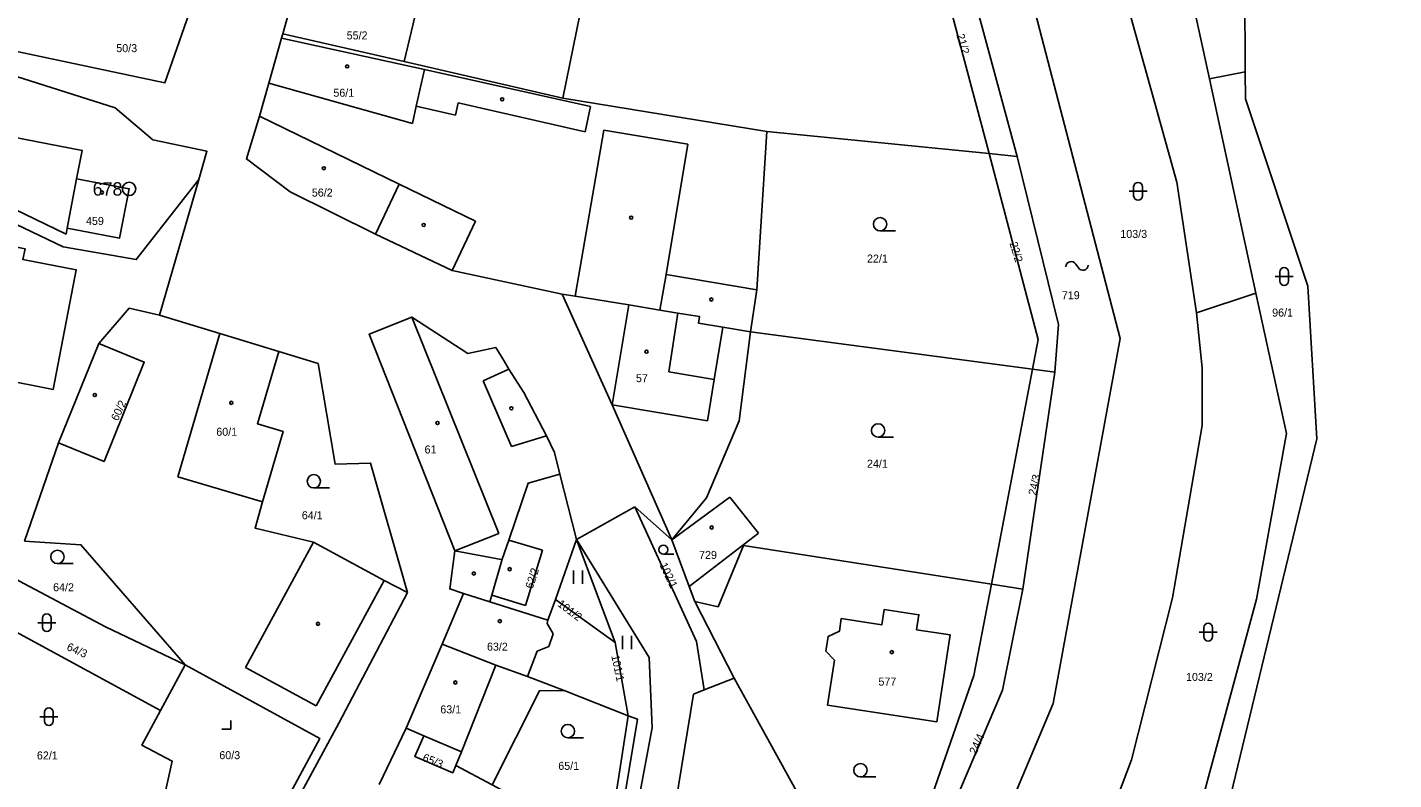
# Model space of a CAD drawing. Extents: x -758582 to -751794, y -998770 to -994350.
# Drawn here: x -755599.9 to -755446.2, y -995816.3 to -995731.7 of the extents above; entities that cross this region are included whole.
import ezdxf

# ---------------------------------------------------------------- set-up
doc = ezdxf.new("R2010")
doc.units = 0
for name, color, linetype in [('Hranice parcel', 7, 'Continuous'), ('Parcelní čísla', 7, 'Continuous'), ('Vnitřní kresba', 7, 'Continuous'), ('Značky bodu BP', 7, 'Continuous'), ('Značky budov', 7, 'Continuous'), ('Značky kultur', 7, 'Continuous')]:
    doc.layers.add(name, color=color, linetype=linetype)

msp = doc.modelspace()

# ---------------------------------------------------------------- linework, layer by layer
at = {"layer": 'Hranice parcel'}
for p, q in [((-755539.7, -995739.68), (-755534.54, -995714.36)), ((-755569.33, -995725.58), (-755571.19, -995732.43)), ((-755571.19, -995732.43), (-755557.56, -995735.57)), ((-755557.56, -995735.57), (-755539.7, -995739.68)), ((-755462.93, -995736.73), (-755466.97, -995737.5)), ((-755466.97, -995737.5), (-755461.74, -995761.6)), ((-755516.76, -995743.43), (-755539.7, -995739.68)), ((-755516.76, -995743.43), (-755491.76, -995745.91)), ((-755491.76, -995745.91), (-755488.58, -995746.23)), ((-755594.4, -995748.74), (-755595.48, -995754.29)), ((-755585.08, -995764.1), (-755580.66, -995748.82)), ((-755461.74, -995761.6), (-755468.42, -995763.84)), ((-755486.86, -995770.17), (-755518.61, -995765.97)), ((-755591.92, -995767.28), (-755596.45, -995778.47)), ((-755491.49, -995794.37), (-755486.86, -995770.17)), ((-755486.86, -995770.17), (-755484.37, -995770.5)), ((-755487.94, -995794.93), (-755484.37, -995770.5)), ((-755596.45, -995778.47), (-755600.27, -995789.5)), ((-755538.17, -995789.33), (-755540.04, -995781.97)), ((-755538.17, -995789.33), (-755531.61, -995785.64)), ((-755527.46, -995789.37), (-755531.61, -995785.64)), ((-755527.46, -995789.37), (-755520.93, -995784.58)), ((-755520.93, -995784.58), (-755517.71, -995788.63)), ((-755517.71, -995788.63), (-755525.51, -995794.6)), ((-755540.55, -995796.06), (-755538.17, -995789.33)), ((-755538.17, -995789.33), (-755533.83, -995800.9)), ((-755525.51, -995794.6), (-755527.46, -995789.37)), ((-755525.51, -995794.6), (-755524.87, -995796.31)), ((-755491.49, -995794.37), (-755487.94, -995794.93)), ((-755550.88, -995795.39), (-755553.28, -995801.09)), ((-755550.88, -995795.39), (-755547.92, -995796.34)), ((-755533.83, -995800.9), (-755540.55, -995796.06)), ((-755524.87, -995796.31), (-755520.42, -995804.92)), ((-755584.98, -995808.56), (-755603.55, -995798.48)), ((-755532.34, -995809.15), (-755533.83, -995800.9)), ((-755553.28, -995801.09), (-755557.34, -995810.55)), ((-755582.21, -995803.41), (-755584.98, -995808.56)), ((-755523.79, -995806.25), (-755520.42, -995804.92)), ((-755520.42, -995804.92), (-755503.98, -995834.78)), ((-755539.54, -995806.3), (-755532.34, -995809.15)), ((-755557.34, -995810.55), (-755560.36, -995816.89)), ((-755557.34, -995810.55), (-755555.34, -995811.41)), ((-755551.75, -995814.75), (-755547.65, -995816.93))]:
    msp.add_line(p, q, dxfattribs=at)
for points in [[(-755468.42, -995763.84), (-755470.62, -995749.14), (-755478.99, -995719.07), (-755478.39, -995706.28), (-755463.07, -995668.72)], [(-755453.09, -995671.77), (-755469.57, -995709.78), (-755470.33, -995722.02), (-755466.97, -995737.5)], [(-755446.24, -995674.42), (-755463.02, -995718.38), (-755462.93, -995736.73)], [(-755616.22, -995731.24), (-755584.47, -995737.95), (-755577.34, -995717.51)], [(-755491.76, -995745.91), (-755498.83, -995719.23), (-755498.52, -995717.76)], [(-755488.58, -995746.23), (-755495.85, -995719.47), (-755495.74, -995717.59)], [(-755489.32, -995719.48), (-755477.02, -995766.71), (-755484.53, -995807.78), (-755498.8, -995841.6), (-755499.31, -995842.18)], [(-755569.33, -995725.58), (-755555.93, -995728.81), (-755557.56, -995735.57)], [(-755580.66, -995748.82), (-755579.74, -995745.65), (-755585.82, -995744.38), (-755590.08, -995740.75), (-755604.38, -995736.24), (-755620.07, -995733.57), (-755625.82, -995735.56), (-755625.48, -995733.29), (-755649.01, -995728.69), (-755649.85, -995733.07), (-755665.81, -995729.99)], [(-755571.19, -995732.43), (-755571.35, -995732.94), (-755572.77, -995738), (-755573.84, -995741.7)], [(-755594.4, -995748.74), (-755593.78, -995745.56), (-755636.88, -995737.19), (-755637.81, -995742), (-755635.94, -995742.36), (-755625.25, -995747.31), (-755602.55, -995751.62), (-755595.59, -995754.97), (-755595.48, -995754.29)], [(-755462.93, -995736.73), (-755462.92, -995739.76), (-755455.88, -995760.84), (-755454.89, -995777.99), (-755468.08, -995832.64)], [(-755573.84, -995741.7), (-755575.31, -995746.51), (-755570.38, -995750.2), (-755560.77, -995754.97)], [(-755573.84, -995741.7), (-755558.11, -995749.36), (-755560.77, -995754.97)], [(-755518.61, -995765.97), (-755517.89, -995761.23), (-755516.76, -995743.43)], [(-755486.86, -995770.17), (-755486.22, -995766.84), (-755491.76, -995745.91)], [(-755484.37, -995770.5), (-755483.94, -995765.15), (-755488.58, -995746.23)], [(-755595.48, -995754.29), (-755589.57, -995755.41), (-755588.5, -995749.89), (-755594.4, -995748.74)], [(-755580.66, -995748.82), (-755587.69, -995757.83), (-755595.9, -995756.4), (-755602.97, -995753.01), (-755603.54, -995755.96)], [(-755605.98, -995769.55), (-755602.92, -995770.14), (-755603.13, -995771.27), (-755597.04, -995772.44), (-755594.45, -995758.99), (-755600.44, -995757.83), (-755600.2, -995756.61), (-755603.54, -995755.96)], [(-755560.77, -995754.97), (-755552.17, -995759.05), (-755539.78, -995761.72)], [(-755539.78, -995761.72), (-755538.32, -995761.96), (-755532.3, -995762.94), (-755528.78, -995763.52), (-755526.77, -995763.85), (-755524.33, -995764.25), (-755524.45, -995764.99), (-755521.71, -995765.45), (-755518.61, -995765.97)], [(-755539.78, -995761.72), (-755534.17, -995774.16), (-755527.46, -995789.37)], [(-755476.21, -995849.9), (-755461.69, -995796.04), (-755458.3, -995777.4), (-755461.74, -995761.6)], [(-755585.08, -995764.1), (-755588.5, -995763.31), (-755591.92, -995767.28)], [(-755571.67, -995768.19), (-755578.28, -995766.17), (-755585.08, -995764.1)], [(-755468.42, -995763.84), (-755467.8, -995770.01), (-755467.78, -995776.5), (-755471.11, -995795.9), (-755475.72, -995814.1), (-755487.9, -995846.2)], [(-755540.04, -995781.97), (-755540.65, -995779.55), (-755541.54, -995777.68), (-755544.08, -995772.79), (-755545.79, -995770.18), (-755546.34, -995769.19), (-755547.26, -995767.73), (-755550.39, -995768.39), (-755556.71, -995764.31), (-755561.48, -995766.22), (-755551.84, -995790.61), (-755552.42, -995794.89), (-755550.88, -995795.39)], [(-755527.46, -995789.37), (-755523.56, -995784.63), (-755519.88, -995775.97), (-755518.61, -995765.97)], [(-755591.92, -995767.28), (-755586.79, -995769.36), (-755591.32, -995780.55), (-755596.45, -995778.47)], [(-755557.18, -995795.28), (-755559.79, -995793.94), (-755567.77, -995789.61), (-755574.32, -995788.07), (-755573.51, -995785.08), (-755571.18, -995777.16), (-755574.06, -995776.31), (-755571.67, -995768.19)], [(-755557.18, -995795.28), (-755561.34, -995780.73), (-755565.32, -995780.85), (-755567.24, -995769.54), (-755571.67, -995768.19)], [(-755547.92, -995796.34), (-755547.7, -995795.58), (-755546.53, -995791.55), (-755545.77, -995789.4), (-755543.62, -995782.98), (-755540.04, -995781.97)], [(-755531.61, -995785.64), (-755524.67, -995800.79), (-755523.79, -995806.25)], [(-755600.27, -995789.5), (-755593.92, -995789.92), (-755582.21, -995803.41)], [(-755538.17, -995789.33), (-755529.99, -995802.59), (-755529.67, -995810.51), (-755533.37, -995830.29), (-755537.81, -995843.47), (-755543.24, -995853.38), (-755548.93, -995861.53)], [(-755524.87, -995796.31), (-755522.24, -995796.89), (-755519.4, -995790), (-755491.49, -995794.37)], [(-755601.63, -995793.41), (-755600.92, -995793.98), (-755591.16, -995799.16), (-755582.21, -995803.41)], [(-755503.98, -995834.78), (-755493.46, -995804.64), (-755491.49, -995794.37)], [(-755570.82, -995820.95), (-755564.91, -995809.98), (-755557.18, -995795.28)], [(-755547.92, -995796.34), (-755541.38, -995798.42), (-755540.55, -995796.06)], [(-755503.98, -995834.78), (-755503.02, -995836.3), (-755490.26, -995806.26), (-755487.94, -995794.93)], [(-755510.11, -995801.88), (-755509.16, -995802.91), (-755509.93, -995807.96), (-755497.64, -995809.84), (-755496.14, -995800.05), (-755499.91, -995799.48), (-755499.65, -995797.79), (-755503.54, -995797.19), (-755503.81, -995798.92), (-755508.39, -995798.22), (-755508.6, -995799.64), (-755509.87, -995800.22), (-755510.11, -995801.88)], [(-755539.54, -995806.3), (-755543.68, -995804.73), (-755547.25, -995803.47), (-755553.28, -995801.09)], [(-755582.21, -995803.41), (-755567.05, -995811.71), (-755571.79, -995820.54)], [(-755547.65, -995816.93), (-755542.35, -995806.35), (-755539.54, -995806.3)], [(-755523.79, -995806.25), (-755525, -995806.73), (-755527.7, -995823.23), (-755527.98, -995825.87)], [(-755584.98, -995808.56), (-755587.07, -995812.46), (-755583.66, -995814.26), (-755586.26, -995825.88)], [(-755547.65, -995816.93), (-755534.64, -995823.96), (-755532.34, -995809.15)], [(-755534.52, -995828.96), (-755531.3, -995809.54), (-755532.34, -995809.15)], [(-755551.75, -995814.75), (-755552.1, -995815.57), (-755556.35, -995813.74), (-755555.34, -995811.41)], [(-755555.34, -995811.41), (-755551.1, -995813.23), (-755551.75, -995814.75)]]:
    msp.add_lwpolyline(points, dxfattribs=at)
at = {"layer": 'Vnitřní kresba'}
for p, q in [((-755555.28, -995736.45), (-755571.35, -995732.94)), ((-755556.19, -995740.59), (-755555.28, -995736.45)), ((-755555.28, -995736.45), (-755536.59, -995740.6)), ((-755572.77, -995738), (-755556.61, -995742.53)), ((-755556.61, -995742.53), (-755556.19, -995740.59)), ((-755556.19, -995740.59), (-755551.78, -995741.61)), ((-755551.47, -995740.22), (-755551.78, -995741.61)), ((-755537.18, -995743.47), (-755551.47, -995740.22)), ((-755536.59, -995740.6), (-755537.18, -995743.47)), ((-755538.32, -995761.96), (-755535.1, -995743.27)), ((-755525.64, -995744.87), (-755535.1, -995743.27)), ((-755528.1, -995759.51), (-755525.64, -995744.87)), ((-755558.11, -995749.36), (-755549.55, -995753.53)), ((-755549.55, -995753.53), (-755552.17, -995759.05)), ((-755528.78, -995763.52), (-755528.1, -995759.51)), ((-755517.89, -995761.23), (-755528.1, -995759.51)), ((-755532.3, -995762.94), (-755534.17, -995774.16)), ((-755527.8, -995770.46), (-755526.77, -995763.85)), ((-755556.71, -995764.31), (-755546.89, -995788.65)), ((-755522.68, -995771.32), (-755521.71, -995765.45)), ((-755578.28, -995766.17), (-755583.02, -995782.28)), ((-755545.79, -995770.18), (-755548.67, -995771.48)), ((-755548.67, -995771.48), (-755545.48, -995778.87)), ((-755522.68, -995771.32), (-755527.8, -995770.46)), ((-755523.45, -995775.96), (-755522.68, -995771.32)), ((-755534.17, -995774.16), (-755523.45, -995775.96)), ((-755545.48, -995778.87), (-755541.54, -995777.68)), ((-755573.51, -995785.08), (-755583.02, -995782.28)), ((-755551.84, -995790.61), (-755546.89, -995788.65)), ((-755575.42, -995803.72), (-755567.77, -995789.61)), ((-755545.77, -995789.4), (-755541.98, -995790.54)), ((-755551.84, -995790.61), (-755546.64, -995791.56)), ((-755546.64, -995791.56), (-755546.53, -995791.55)), ((-755541.98, -995790.54), (-755543.92, -995796.76)), ((-755567.44, -995808.05), (-755559.79, -995793.94)), ((-755543.92, -995796.76), (-755547.7, -995795.58)), ((-755541.47, -995798.76), (-755541.38, -995798.42)), ((-755540.81, -995799.94), (-755541.47, -995798.76)), ((-755541.28, -995801.36), (-755540.81, -995799.94)), ((-755543.68, -995804.73), (-755542.61, -995801.87)), ((-755542.61, -995801.87), (-755541.28, -995801.36)), ((-755575.42, -995803.72), (-755567.44, -995808.05)), ((-755551.1, -995813.23), (-755547.25, -995803.47))]:
    msp.add_line(p, q, dxfattribs=at)
at = {"layer": 'Značky bodu BP'}
for radius in [0.75, 0.03]:
    msp.add_circle((-755588.5, -995749.89), radius, dxfattribs=at)
at = {"layer": 'Značky budov'}
msp.add_line((-755482.01, -995758.35), (-755481.71, -995758.75), dxfattribs=at)
for centre in [(-755563.97, -995736.11), (-755546.53, -995739.81), (-755566.59, -995747.56), (-755591.55, -995750.29), (-755532.02, -995753.12), (-755555.36, -995753.94), (-755523, -995762.33), (-755530.3, -995768.2), (-755592.36, -995773.08), (-755577.01, -995773.95), (-755545.5, -995774.56), (-755553.81, -995776.22), (-755522.96, -995787.98), (-755549.72, -995793.15), (-755545.68, -995792.67), (-755567.25, -995798.82), (-755546.8, -995798.52), (-755502.69, -995802), (-755551.79, -995805.41)]:
    msp.add_circle(centre, 0.175, dxfattribs=at)
for centre, start, end in [((-755482.52, -995758.64), 29.2914, 181.2189), ((-755481.2, -995758.46), 209.2914, 1.2189)]:
    msp.add_arc(centre, 0.588, start, end, dxfattribs=at)
at = {"layer": 'Značky kultur'}
for p, q in [((-755475.99, -995750.15), (-755473.99, -995750.15)), ((-755475.49, -995749.65), (-755475.49, -995750.65)), ((-755474.49, -995750.65), (-755474.49, -995749.65)), ((-755504.02, -995754.61), (-755502.27, -995754.61)), ((-755459.06, -995759.24), (-755459.06, -995760.24)), ((-755458.06, -995760.24), (-755458.06, -995759.24)), ((-755459.56, -995759.74), (-755457.56, -995759.74)), ((-755504.24, -995777.81), (-755502.49, -995777.81)), ((-755567.72, -995783.53), (-755565.97, -995783.53)), ((-755528.39, -995790.97), (-755527.21, -995790.97)), ((-755596.56, -995792.03), (-755594.81, -995792.03)), ((-755538.51, -995794.33), (-755538.51, -995792.83)), ((-755537.51, -995794.33), (-755537.51, -995792.83)), ((-755598.76, -995798.69), (-755596.76, -995798.69)), ((-755598.26, -995798.19), (-755598.26, -995799.19)), ((-755597.26, -995799.19), (-755597.26, -995798.19)), ((-755467.61, -995799.25), (-755467.61, -995800.25)), ((-755466.61, -995800.25), (-755466.61, -995799.25)), ((-755532.98, -995801.67), (-755532.98, -995800.17)), ((-755531.98, -995801.67), (-755531.98, -995800.17)), ((-755468.11, -995799.75), (-755466.11, -995799.75)), ((-755598.53, -995809.26), (-755596.53, -995809.26)), ((-755598.03, -995808.76), (-755598.03, -995809.76)), ((-755597.03, -995809.76), (-755597.03, -995808.76)), ((-755577.05, -995810.68), (-755577.05, -995809.68)), ((-755578.05, -995810.68), (-755577.05, -995810.68)), ((-755539.14, -995811.63), (-755537.39, -995811.63)), ((-755506.23, -995816.03), (-755504.48, -995816.03))]:
    msp.add_line(p, q, dxfattribs=at)
for centre, radius in [((-755504.02, -995753.86), 0.75), ((-755504.24, -995777.06), 0.75), ((-755567.72, -995782.78), 0.75), ((-755528.39, -995790.47), 0.502), ((-755596.56, -995791.28), 0.75), ((-755539.14, -995810.88), 0.75), ((-755506.23, -995815.28), 0.75)]:
    msp.add_circle(centre, radius, dxfattribs=at)
for centre, start, end in [((-755474.99, -995749.65), 0, 180), ((-755474.99, -995750.65), 180, 359.9879), ((-755458.56, -995759.24), 0, 180), ((-755458.56, -995760.24), 180, 359.9879), ((-755597.76, -995798.19), 0, 180), ((-755597.76, -995799.19), 180, 359.9879), ((-755467.11, -995799.25), 0, 180), ((-755467.11, -995800.25), 180, 359.9879), ((-755597.53, -995808.76), 0, 180), ((-755597.53, -995809.76), 180, 359.9879)]:
    msp.add_arc(centre, 0.5, start, end, dxfattribs=at)

# ---------------------------------------------------------------- texts
at = {"layer": 'Parcelní čísla'}
for s, p in [('55/2', (-755564.02, -995733.07)), ('50/3', (-755589.94, -995734.5)), ('56/1', (-755565.52, -995739.52)), ('56/2', (-755567.94, -995750.75)), ('459', (-755593.35, -995753.94)), ('103/3', (-755476.99, -995755.4)), ('22/1', (-755505.49, -995758.17)), ('719', (-755483.57, -995762.3)), ('96/1', (-755459.91, -995764.25)), ('57', (-755531.48, -995771.63)), ('60/1', (-755578.69, -995777.66)), ('61', (-755555.26, -995779.65)), ('24/1', (-755505.49, -995781.25)), ('64/1', (-755569.07, -995787.05)), ('729', (-755524.38, -995791.51)), ('64/2', (-755597.05, -995795.15)), ('63/2', (-755548.24, -995801.83)), ('577', (-755504.2, -995805.76)), ('103/2', (-755469.6, -995805.24)), ('63/1', (-755553.49, -995808.89)), ('62/1', (-755598.87, -995814.07)), ('60/3', (-755578.35, -995814.04)), ('65/1', (-755540.22, -995815.24))]:
    msp.add_text(s, height=0.9, dxfattribs=at).set_placement(p)
for s, rotation, p in [('21/2', 286, (-755495.44, -995732.57)), ('22/2', 287, (-755489.47, -995756)), ('60/2', 65, (-755589.77, -995776.06)), ('24/3', 77, (-755486.49, -995784.41)), ('62/2', 72, (-755543.1, -995794.94)), ('102/1', 295, (-755528.85, -995792.18)), ('101/2', 323, (-755540.38, -995796.75)), ('64/3', 336, (-755595.6, -995801.72)), ('101/1', 282, (-755534.26, -995802.42)), ('24/4', 66, (-755493.21, -995813.57)), ('65/3', 338, (-755555.57, -995814.2))]:
    msp.add_text(s, height=0.9, rotation=rotation, dxfattribs=at).set_placement(p)
at = {"layer": 'Značky bodu BP'}
msp.add_text('678', height=1.5, dxfattribs=at).set_placement((-755592.6, -995750.64))

doc.saveas('drawing.dxf')
